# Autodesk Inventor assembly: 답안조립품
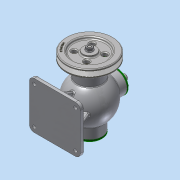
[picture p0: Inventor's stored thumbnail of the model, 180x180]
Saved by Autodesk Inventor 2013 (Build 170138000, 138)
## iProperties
Created: 2018-06
Part Number: 답안조립품
Document SubType Name: Assembly
Designer: Administrator
Author: Administrator
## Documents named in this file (19)
- C:\Users\Administrator\Desktop\480612V1008\답안조립품.iam
- C:\Users\Administrator\Desktop\480612V1008\본체.ipt
- C:\Users\Administrator\Desktop\480612V1008\V-벨트풀리.ipt
- C:\Users\Administrator\Desktop\480612V1008\너트 M8.ipt
- C:\Users\Administrator\Desktop\480612V1008\뒤커버.ipt
- C:\Users\Administrator\Desktop\480612V1008\멈춤링 15x1.ipt
- C:\Users\Administrator\Desktop\480612V1008\멈춤링 35x1.6.ipt
- 멈춤링 35x1.6.ipt
- C:\Users\Administrator\Desktop\480612V1008\베어링 6202.ipt
- 베어링 6202.ipt
- C:\Users\Administrator\Desktop\480612V1008\볼트 M4x12.ipt
- C:\Users\Administrator\Desktop\480612V1008\볼트 M4x16.ipt
- C:\Users\Administrator\Desktop\480612V1008\부시.ipt
- C:\Users\Administrator\Desktop\480612V1008\상부커버.ipt
- C:\Users\Administrator\Desktop\480612V1008\슬라이드.ipt
- C:\Users\Administrator\Desktop\480612V1008\앞커버.ipt
- C:\Users\Administrator\Desktop\480612V1008\오일 실 15 30 7.ipt
- C:\Users\Administrator\Desktop\480612V1008\키 4x4x12.ipt
- C:\Users\Administrator\Desktop\480612V1008\편심축.ipt
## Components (1 placed, 1 different names)
1. V-벨트풀리:1
